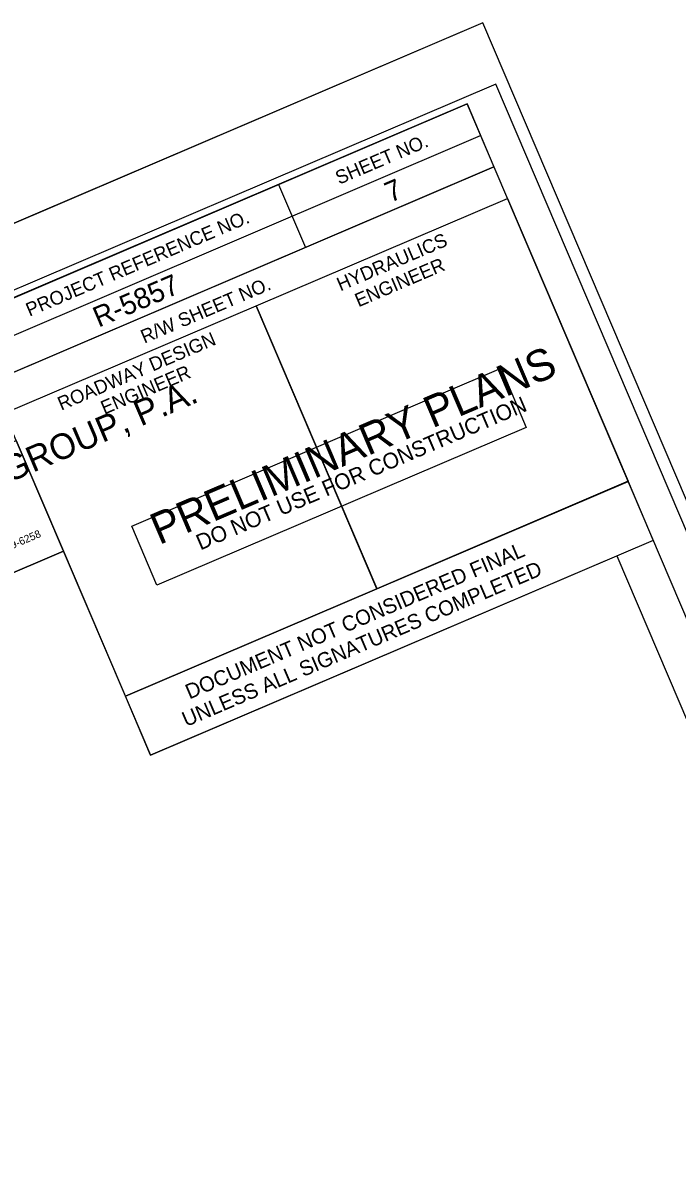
# Model space of a CAD drawing. Extents: x 2192740 to 2194721, y 86011 to 87688.
# Drawn here: x 2194120.8 to 2194360.3, y 87266.9 to 87684.3 of the extents above; entities that cross this region are included whole.
import ezdxf

# ---------------------------------------------------------------- set-up
doc = ezdxf.new("R2010")
doc.units = 0
for name, color, linetype in [('CTL Primary Horizontal CELL', 7, 'Continuous'), ('CTL Primary Horizontal Cogo Comment', 7, 'Continuous'), ('CTL Primary Horizontal Cogo Elevation', 7, 'Continuous'), ('CTL Primary Horizontal Cogo Number', 7, 'Continuous'), ('Exist Other Culture Sign', 7, 'Continuous'), ('Exist Roads EOP Other', 7, 'Continuous'), ('Exist Structure Minor Storm Sewer Manhole CELL', 7, 'Continuous'), ('Exist Utilities Other Traffic Signal Box CELL', 7, 'Continuous')]:
    doc.layers.add(name, color=color, linetype=linetype)

msp = doc.modelspace()

# ---------------------------------------------------------------- linework, layer by layer
at = {"layer": 'CTL Primary Horizontal Cogo Comment'}
msp.add_line((2194289.19, 87684.26), (2192740.45, 87023.01), dxfattribs=at)
at = {"layer": 'CTL Primary Horizontal Cogo Elevation'}
msp.add_lwpolyline([(2194289.19, 87684.26), (2192740.45, 87023.01), (2193172.38, 86011.36), (2194721.13, 86672.62)], close=True, dxfattribs=at)
at = {"layer": 'CTL Primary Horizontal Cogo Number'}
msp.add_lwpolyline([(2194293.87, 87661.85), (2192761.22, 87007.47), (2193175.52, 86037.12), (2194708.17, 86691.5)], close=True, dxfattribs=at)
at = {"layer": 'Exist Other Culture Sign'}
for p, q in [((2194104.32, 87564.5), (2194288.3, 87643.06)), ((2194109.23, 87553.01), (2194293.21, 87631.56)), ((2194109.23, 87553.01), (2194293.21, 87631.56)), ((2194214.42, 87625.1), (2194224.23, 87602.11)), ((2194206.15, 87580.8), (2194250.31, 87477.38))]:
    msp.add_line(p, q, dxfattribs=at)
for points in [[(2194283.37, 87654.6), (2192903.85, 87065.6), (2193316.15, 86099.93), (2194695.67, 86688.93)], [(2194099.39, 87576.04), (2194283.37, 87654.6), (2194293.21, 87631.56), (2194109.23, 87553.01)], [(2194206.15, 87580.8), (2194298.12, 87620.06), (2194342.29, 87516.6), (2194250.33, 87477.33)], [(2194114.14, 87541.51), (2194206.15, 87580.8), (2194250.33, 87477.33), (2194158.31, 87438.05)], [(2193994.8, 87478.73), (2194118.41, 87531.51), (2194135.69, 87491.03), (2194012.09, 87438.25)]]:
    msp.add_lwpolyline(points, close=True, dxfattribs=at)
at = {"layer": 'Exist Roads EOP Other'}
msp.add_lwpolyline([(2194169.87, 87478.59), (2194160.64, 87500.2), (2194295.83, 87557.93), (2194305.06, 87536.31)], close=True, dxfattribs=at)
at = {"layer": 'Exist Structure Minor Storm Sewer Manhole CELL'}
for p, q in [((2194158.31, 87438.05), (2194342.28, 87516.59)), ((2194342.29, 87516.58), (2194351.52, 87494.97)), ((2194351.51, 87494.98), (2194167.54, 87416.43)), ((2194167.54, 87416.43), (2194158.31, 87438.05))]:
    msp.add_line(p, q, dxfattribs=at)
at = {"layer": 'Exist Utilities Other Traffic Signal Box CELL'}
msp.add_lwpolyline([(2194135.69, 87491.03), (2194167.54, 87416.43), (2194338.24, 87489.32), (2194682.39, 86683.26), (2193316.15, 86099.93), (2193239.14, 86280.31), (2193214.47, 87198.22), (2193975.79, 87523.27), (2194012.09, 87438.25)], close=True, dxfattribs=at)

# ---------------------------------------------------------------- texts
at = {"layer": 'CTL Primary Horizontal CELL'}
for s, p in [('7', (2194255.29, 87618.41)), ('R-5857', (2194148.51, 87572.77))]:
    msp.add_text(s, height=7.5, rotation=23.1206, dxfattribs=at).set_placement(p)
at = {"layer": 'Exist Other Culture Sign'}
for s, height, p in [('SHEET NO.', 5, (2194236.52, 87625.03)), ('PROJECT REFERENCE NO.', 5.0001, (2194123.23, 87576.76)), ('HYDRAULICS', 5, (2194237.02, 87586.04)), ('ENGINEER', 5, (2194243.64, 87580.22)), ('R/W SHEET NO.', 5.0001, (2194165.26, 87566.93)), ('ROADWAY DESIGN', 5.0001, (2194134.85, 87542.41)), ('ENGINEER', 5, (2194150.64, 87540.95)), ('SUNGATE DESIGN GROUP, P.A.', 9.3194, (2194009.82, 87470.8)), ('TEL (919) 859-2243   FAX (919) 859-6258', 2.8007, (2194062.79, 87468.69))]:
    msp.add_text(s, height=height, rotation=23.1206, dxfattribs=at).set_placement(p)
at = {"layer": 'Exist Roads EOP Other'}
for s, height, p in [('PRELIMINARY PLANS', 11.52, (2194170.68, 87493.24)), ('DO NOT USE FOR CONSTRUCTION', 5.76, (2194185.76, 87491.3))]:
    msp.add_text(s, height=height, rotation=23.1206, dxfattribs=at).set_placement(p)
at = {"layer": 'Exist Structure Minor Storm Sewer Manhole CELL'}
for s, p in [('DOCUMENT NOT CONSIDERED FINAL', (2194181.75, 87436.81)), ('UNLESS ALL SIGNATURES COMPLETED', (2194180.54, 87426.72))]:
    msp.add_text(s, height=5.5, rotation=23.1206, dxfattribs=at).set_placement(p)

doc.saveas('drawing.dxf')
